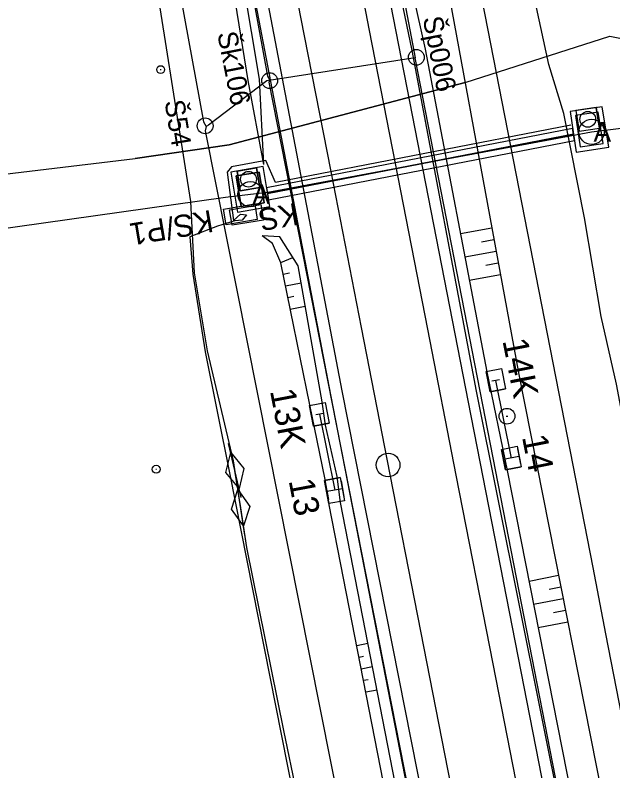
# Model space of a CAD drawing. Extents: x -545967 to -545044, y -1122650 to -1118491.
# Drawn here: x -545839.89 to -545802.07, y -1118710.23 to -1118662.41 of the extents above; entities that cross this region are included whole.
import ezdxf

# ---------------------------------------------------------------- set-up
doc = ezdxf.new("R2010")
doc.units = 0
for name, color, linetype in [('Vrstva 1', 7, 'Continuous'), ('Vrstva 1 - Koleje', 7, 'Continuous'), ('Vrstva 11 - Trakce', 7, 'Continuous'), ('Vrstva 12 - Trakce zaklady', 7, 'Continuous'), ('Vrstva 19 - Staniceni', 7, 'Continuous'), ('Vrstva 25 - silnoproud prvky', 7, 'Continuous'), ('Vrstva 26', 7, 'Continuous'), ('Vrstva 26 - silnoproud', 7, 'Continuous'), ('Vrstva 28 - zabzar', 7, 'Continuous'), ('Vrstva 31', 7, 'Continuous'), ('Vrstva 32', 7, 'Continuous'), ('Vrstva 33 - prvky sdelzar', 7, 'Continuous'), ('Vrstva 4 - Teren - stezky - prechody - plochy', 7, 'Continuous'), ('Vrstva 41', 7, 'Continuous'), ('Vrstva 42', 7, 'Continuous'), ('Vrstva 43', 7, 'Continuous'), ('Vrstva 44', 7, 'Continuous'), ('Vrstva 47', 7, 'Continuous'), ('Vrstva 48', 7, 'Continuous'), ('Vrstva 49', 7, 'Continuous'), ('Vrstva 50', 7, 'Continuous'), ('Vrstva 7 - Namezniky-vystroj', 7, 'Continuous')]:
    doc.layers.add(name, color=color, linetype=linetype)

msp = doc.modelspace()

# ---------------------------------------------------------------- linework, layer by layer
at = {"layer": 'Vrstva 1'}
for points in [[(-545825.931, -1118581.521), (-545824.016, -1118591.357), (-545817.098, -1118626.815), (-545815.58, -1118634.584), (-545810.799, -1118659.197), (-545810.531, -1118660.549), (-545805.871, -1118684.414), (-545803.343, -1118697.361)], [(-545803.343, -1118697.361), (-545802.529, -1118701.559), (-545796.372, -1118733.137), (-545788.892, -1118771.626), (-545784.123, -1118796.192), (-545777.723, -1118829.089), (-545771.163, -1118862.699), (-545764.792, -1118895.381), (-545757.603, -1118932.309), (-545753.441, -1118953.648), (-545749.904, -1118971.286), (-545746.403, -1118987.4), (-545742.64, -1119003.664), (-545739.307, -1119017.411), (-545735.997, -1119030.103), (-545730.526, -1119049.438)]]:
    msp.add_lwpolyline(points, dxfattribs=at)
at = {"layer": 'Vrstva 1 - Koleje'}
for points in [[(-545844.611, -1118524.236), (-545843.323, -1118530.854), (-545841.995, -1118537.671), (-545840.062, -1118547.589), (-545838.151, -1118557.387), (-545836.187, -1118567.479), (-545834.293, -1118577.171), (-545832.142, -1118588.194), (-545830.344, -1118597.44), (-545828.848, -1118605.077), (-545828.138, -1118608.718), (-545827.12, -1118613.935), (-545825.269, -1118623.436), (-545823.266, -1118633.717), (-545821.486, -1118642.857), (-545818.722, -1118657.024), (-545817.482, -1118663.386), (-545815.845, -1118671.798), (-545813.797, -1118682.286), (-545811.996, -1118691.52), (-545809.67, -1118703.454), (-545807.882, -1118712.632)], [(-545848.628, -1118525.023), (-545847.323, -1118531.712), (-545846.098, -1118538.003), (-545844.166, -1118547.957), (-545842.342, -1118557.292), (-545840.544, -1118566.52), (-545838.785, -1118575.544), (-545836.613, -1118586.684), (-545834.863, -1118595.653), (-545833.089, -1118604.755), (-545832.153, -1118609.557), (-545831.329, -1118613.781), (-545829.452, -1118623.418), (-545827.682, -1118632.501), (-545825.51, -1118643.639), (-545823.563, -1118653.595), (-545821.825, -1118662.539), (-545819.916, -1118672.31), (-545817.993, -1118682.172), (-545816.178, -1118691.474), (-545814.43, -1118700.429), (-545812.52, -1118710.222), (-545810.747, -1118719.317)]]:
    msp.add_lwpolyline(points, dxfattribs=at)
at = {"layer": 'Vrstva 11 - Trakce'}
for p, q in [((-545809.244, -1118685.485), (-545809.734, -1118685.582)), ((-545809.492, -1118685.534), (-545808.501, -1118690.437)), ((-545820.376, -1118687.622), (-545820.868, -1118687.715)), ((-545820.625, -1118687.669), (-545819.669, -1118692.474)), ((-545809.089, -1118690.044), (-545808.894, -1118691.025)), ((-545808.108, -1118689.849), (-545807.913, -1118690.83)), ((-545808.011, -1118690.34), (-545808.991, -1118690.534)), ((-545820.253, -1118692.075), (-545820.068, -1118693.058)), ((-545819.27, -1118691.89), (-545819.085, -1118692.873)), ((-545819.178, -1118692.382), (-545820.16, -1118692.566))]:
    msp.add_line(p, q, dxfattribs=at)
at = {"layer": 'Vrstva 12 - Trakce zaklady'}
for p, q in [((-545810.095, -1118684.967), (-545809.114, -1118684.775)), ((-545809.843, -1118686.252), (-545808.862, -1118686.06)), ((-545821.261, -1118687.11), (-545820.279, -1118686.922)), ((-545809.11, -1118689.891), (-545808.129, -1118689.697)), ((-545808.855, -1118691.18), (-545807.874, -1118690.986)), ((-545819.334, -1118691.666), (-545820.317, -1118691.85)), ((-545819.058, -1118693.137), (-545820.041, -1118693.321))]:
    msp.add_line(p, q, dxfattribs=at)
for points in [[(-545809.843, -1118686.252), (-545810.095, -1118684.967), (-545809.114, -1118684.775), (-545808.862, -1118686.06), (-545809.843, -1118686.252)], [(-545810.095, -1118684.967), (-545810.095, -1118684.967), (-545809.843, -1118686.252), (-545809.843, -1118686.252)], [(-545820.279, -1118686.922), (-545820.029, -1118688.231), (-545821.011, -1118688.419), (-545821.261, -1118687.11), (-545820.279, -1118686.922)], [(-545820.279, -1118686.922), (-545820.279, -1118686.922), (-545820.029, -1118688.231), (-545820.029, -1118688.231)], [(-545821.261, -1118687.11), (-545821.261, -1118687.11), (-545821.011, -1118688.419)], [(-545821.011, -1118688.419), (-545821.011, -1118688.419), (-545820.029, -1118688.231)], [(-545808.855, -1118691.18), (-545809.11, -1118689.891), (-545808.129, -1118689.697), (-545807.874, -1118690.986), (-545808.855, -1118691.18)], [(-545808.129, -1118689.697), (-545808.129, -1118689.697), (-545807.874, -1118690.986), (-545807.874, -1118690.986)], [(-545809.11, -1118689.891), (-545809.11, -1118689.891), (-545808.855, -1118691.18), (-545808.855, -1118691.18)], [(-545819.334, -1118691.666), (-545819.058, -1118693.137), (-545820.041, -1118693.321), (-545820.317, -1118691.85), (-545819.334, -1118691.666)], [(-545819.334, -1118691.666), (-545819.334, -1118691.666), (-545819.058, -1118693.137), (-545819.058, -1118693.137)], [(-545820.317, -1118691.85), (-545820.317, -1118691.85), (-545820.041, -1118693.321), (-545820.041, -1118693.321)]]:
    msp.add_lwpolyline(points, dxfattribs=at)
at = {"layer": 'Vrstva 19 - Staniceni'}
msp.add_circle((-545816.294, -1118690.878), 0.75, dxfattribs=at)
at = {"layer": 'Vrstva 25 - silnoproud prvky'}
for points in [[(-545826.538, -1118675.676), (-545826.706, -1118674.69), (-545824.734, -1118674.356), (-545824.566, -1118675.342), (-545826.538, -1118675.676)], [(-545826.155, -1118675.712), (-545826.323, -1118674.726), (-545824.351, -1118674.392), (-545824.183, -1118675.378), (-545826.155, -1118675.712)]]:
    msp.add_lwpolyline(points, dxfattribs=at)
at = {"layer": 'Vrstva 26'}
msp.add_lwpolyline([(-545795.14, -1118719.856), (-545797.401, -1118709.038), (-545800.896, -1118690.8), (-545801.851, -1118685.761), (-545802.818, -1118681.484), (-545803.86, -1118675.25), (-545805.172, -1118668.631), (-545806.131, -1118665.54), (-545807.231, -1118660.35), (-545808.894, -1118651.177), (-545811.62, -1118637.176), (-545812.724, -1118631.013), (-545813.605, -1118626.947), (-545815.439, -1118615.53)], dxfattribs=at)
at = {"layer": 'Vrstva 26 - silnoproud'}
for points in [[(-545795.14, -1118719.856), (-545797.401, -1118709.038), (-545800.896, -1118690.8), (-545801.851, -1118685.761), (-545802.818, -1118681.484), (-545803.86, -1118675.25), (-545805.172, -1118668.631), (-545806.131, -1118665.54), (-545807.231, -1118660.35), (-545808.894, -1118651.177), (-545811.62, -1118637.176), (-545812.724, -1118631.013), (-545813.605, -1118626.947), (-545815.439, -1118615.53)], [(-545804.723, -1118669.38), (-545823.422, -1118673.004), (-545824.024, -1118671.607), (-545826.19, -1118672.019), (-545826.479, -1118672.345), (-545826.082, -1118675.405), (-545825.636, -1118675.016), (-545825.253, -1118675.052), (-545825.524, -1118675.387), (-545825.985, -1118675.439), (-545827.078, -1118675.764), (-545828.843, -1118676.437), (-545828.656, -1118678.804), (-545827.868, -1118683.721), (-545826.321, -1118691.367), (-545821.946, -1118713.57), (-545816.92, -1118739.132), (-545813.046, -1118758.857), (-545808.289, -1118783.504), (-545803.049, -1118810.067), (-545800.897, -1118821.514), (-545796.684, -1118843.318)], [(-545804.723, -1118669.38), (-545823.422, -1118673.004)]]:
    msp.add_lwpolyline(points, dxfattribs=at)
at = {"layer": 'Vrstva 28 - zabzar'}
for p, q in [((-545825.583, -1118692.925), (-545826.385, -1118689.527)), ((-545826.55, -1118691.36), (-545826.251, -1118690.094)), ((-545826.251, -1118690.094), (-545825.418, -1118691.092)), ((-545825.418, -1118691.092), (-545825.717, -1118692.358)), ((-545825.717, -1118692.358), (-545826.55, -1118691.36)), ((-545825.351, -1118695.31), (-545825.887, -1118691.86)), ((-545826.194, -1118693.674), (-545825.797, -1118692.435)), ((-545825.797, -1118692.435), (-545825.044, -1118693.496)), ((-545825.044, -1118693.496), (-545825.441, -1118694.735)), ((-545825.441, -1118694.735), (-545826.194, -1118693.674))]:
    msp.add_line(p, q, dxfattribs=at)
for points in [[(-545825.23, -1118696.09), (-545825.619, -1118693.585), (-545825.984, -1118691.226), (-545826.08, -1118690.61), (-545827.72, -1118683.66), (-545828.55, -1118678.72), (-545828.78, -1118674.2), (-545831.46, -1118657.27), (-545836.43, -1118633.48), (-545838.77, -1118619), (-545839.17, -1118613.92), (-545839.25, -1118611.04), (-545838.43, -1118605.08), (-545838.36, -1118603.32)], [(-545759.72, -1119031.91), (-545759.89, -1119030.77), (-545763.23, -1119013.33), (-545766.25, -1118997.62), (-545768.86, -1118984.55), (-545771, -1118974.69), (-545771.8, -1118970.9), (-545773.86, -1118959.07), (-545776.3, -1118946.17), (-545780.31, -1118924.98), (-545785.87, -1118897.11), (-545790.99, -1118870.65), (-545796.29, -1118843.25), (-545799.19, -1118827.63), (-545805.85, -1118794.17), (-545808.2, -1118783.5), (-545812.82, -1118758.82), (-545816.62, -1118739.16), (-545820.43, -1118719.58), (-545822.89, -1118707.67), (-545825.23, -1118696.09)]]:
    msp.add_lwpolyline(points, dxfattribs=at)
at = {"layer": 'Vrstva 31'}
msp.add_lwpolyline([(-545850.96, -1118681.13), (-545850.51, -1118680.46), (-545848.78, -1118676.81), (-545847.44, -1118674.83), (-545847.15, -1118673.7), (-545846.77, -1118673.1), (-545844.1, -1118672.89), (-545832.3, -1118671.48), (-545826.35, -1118670.63), (-545811.42, -1118666.68), (-545802.26, -1118663.75), (-545801.2, -1118663.96), (-545800.56, -1118664.54), (-545799.84, -1118666.21), (-545798.21, -1118668.15), (-545796.54, -1118669.87), (-545795.09, -1118671.42), (-545794.4, -1118671.8)], dxfattribs=at)
msp.add_lwpolyline([(-545850.96, -1118681.13), (-545850.51, -1118680.46), (-545848.78, -1118676.81), (-545847.44, -1118674.83), (-545847.15, -1118673.7), (-545846.77, -1118673.1), (-545844.1, -1118672.89), (-545832.3, -1118671.48), (-545826.35, -1118670.63), (-545811.42, -1118666.68), (-545802.26, -1118663.75), (-545801.2, -1118663.96), (-545800.56, -1118664.54), (-545799.84, -1118666.21), (-545798.21, -1118668.15), (-545796.54, -1118669.87), (-545795.09, -1118671.42), (-545794.4, -1118671.8)], dxfattribs=at)
at = {"layer": 'Vrstva 32'}
msp.add_lwpolyline([(-545820.43, -1118719.58), (-545822.89, -1118707.67), (-545825.23, -1118696.09), (-545826.08, -1118690.61), (-545827.72, -1118683.66), (-545828.55, -1118678.72), (-545828.78, -1118674.2), (-545831.46, -1118657.27), (-545836.43, -1118633.48), (-545838.77, -1118619)], dxfattribs=at)
at = {"layer": 'Vrstva 33 - prvky sdelzar'}
msp.add_lwpolyline([(-545811.42, -1118666.68), (-545826.35, -1118670.63), (-545832.3, -1118671.48)], dxfattribs=at)
at = {"layer": 'Vrstva 4 - Teren - stezky - prechody - plochy'}
for points in [[(-545842.057, -1118523.737), (-545841.08, -1118528.803), (-545840.285, -1118532.869), (-545839.902, -1118534.493), (-545835.95, -1118554.692), (-545830.173, -1118584.852), (-545827.402, -1118599.381), (-545819.669, -1118640.626), (-545818.68, -1118644.829), (-545817.556, -1118652.409), (-545817.153, -1118653.253), (-545814.795, -1118664.646), (-545810.716, -1118686.202), (-545798.466, -1118747.292), (-545787.709, -1118802.92), (-545777.141, -1118857.583)], [(-545842.991, -1118523.919), (-545841.705, -1118530.396), (-545836.849, -1118554.447), (-545831.054, -1118584.604), (-545819.351, -1118645.264), (-545811.232, -1118686.911), (-545799.532, -1118746.647), (-545788.535, -1118802.768), (-545777.847, -1118857.696), (-545765.826, -1118919.341), (-545755.98, -1118970.183), (-545745.509, -1119023.121), (-545734.813, -1119078.883), (-545723.148, -1119138.675), (-545711.327, -1119199.256), (-545707.51, -1119218.932), (-545706.355, -1119218.803)], [(-545711.324, -1119247.435), (-545711.901, -1119243.963), (-545720.224, -1119201.665), (-545721.285, -1119195.757), (-545731.546, -1119141.712), (-545737.081, -1119112.42), (-545743.441, -1119079.103), (-545754.278, -1119022.005), (-545764.127, -1118971.243), (-545774.702, -1118917.119), (-545786.098, -1118858.181), (-545797.005, -1118803.413), (-545807.661, -1118749.422), (-545819.911, -1118686.431), (-545828.531, -1118641.36), (-545850.15, -1118530.525), (-545851.156, -1118525.517)], [(-545710.225, -1119247.22), (-545719.004, -1119201.386), (-545730.622, -1119141.385), (-545736.208, -1119112.206), (-545742.564, -1119078.927), (-545753.414, -1119021.814), (-545763.359, -1118970.942), (-545773.922, -1118916.709), (-545785.328, -1118858.188), (-545796.206, -1118802.914), (-545806.845, -1118748.63), (-545819.206, -1118686.191), (-545827.818, -1118641.013), (-545849.345, -1118530.249), (-545850.409, -1118525.371)]]:
    msp.add_lwpolyline(points, dxfattribs=at)
at = {"layer": 'Vrstva 41'}
for centre, radius in [((-545803.659, -1118669.008), 0.5), ((-545803.414, -1118669.801), 0.8), ((-545825.129, -1118672.799), 0.5), ((-545824.998, -1118673.746), 0.8)]:
    msp.add_circle(centre, radius, dxfattribs=at)
at = {"layer": 'Vrstva 42'}
msp.add_lwpolyline([(-545847.978, -1118676.939), (-545826.574, -1118673.927), (-545824.998, -1118673.746), (-545823.896, -1118673.62), (-545803.414, -1118669.801), (-545799.147, -1118669.27), (-545796.625, -1118671.347), (-545795.259, -1118671.153)], dxfattribs=at)
at = {"layer": 'Vrstva 43'}
for centre in [(-545814.504, -1118665.085), (-545823.786, -1118666.557), (-545827.871, -1118669.417)]:
    msp.add_circle(centre, 0.5, dxfattribs=at)
at = {"layer": 'Vrstva 44'}
for points in [[(-545846.223, -1118571.979), (-545846.221, -1118572.119), (-545836.892, -1118620.467), (-545827.979, -1118669.157), (-545827.809, -1118669.462), (-545827.871, -1118669.728), (-545818.616, -1118716.33), (-545818.55, -1118716.796), (-545818.473, -1118717.196), (-545808.913, -1118765.432), (-545808.826, -1118765.882), (-545808.745, -1118766.383), (-545799.375, -1118814.752), (-545799.301, -1118815.001), (-545799.29, -1118815.321), (-545789.933, -1118863.748)], [(-545823.989, -1118615.966), (-545823.909, -1118616.115), (-545814.588, -1118665.112), (-545823.538, -1118666.512), (-545823.785, -1118666.525)], [(-545833.154, -1118618.242), (-545828.365, -1118642.955), (-545827.522, -1118644.179), (-545826.938, -1118646.983), (-545827.134, -1118648.756), (-545823.92, -1118666.279), (-545823.785, -1118666.525)], [(-545805.038, -1118714.002), (-545814.588, -1118665.112)], [(-545823.785, -1118666.525), (-545823.975, -1118666.575), (-545827.65, -1118669.368), (-545827.809, -1118669.462)], [(-545814.194, -1118715.513), (-545823.815, -1118666.664), (-545823.785, -1118666.525)]]:
    msp.add_lwpolyline(points, dxfattribs=at)
at = {"layer": 'Vrstva 47'}
for p, q in [((-545803.116, -1118668.267), (-545803.117, -1118668.267)), ((-545804.406, -1118668.45), (-545804.406, -1118668.45)), ((-545802.992, -1118668.551), (-545802.992, -1118668.551)), ((-545804.439, -1118668.766), (-545804.439, -1118668.766)), ((-545823.983, -1118673.314), (-545804.623, -1118669.556)), ((-545804.505, -1118670.349), (-545804.623, -1118669.557)), ((-545802.924, -1118669.557), (-545802.924, -1118669.557)), ((-545823.918, -1118673.709), (-545804.564, -1118669.953)), ((-545804.564, -1118669.953), (-545823.918, -1118673.709)), ((-545804.202, -1118669.749), (-545804.202, -1118669.749)), ((-545823.853, -1118674.104), (-545804.504, -1118670.349)), ((-545802.674, -1118670.527), (-545802.674, -1118670.527)), ((-545804.141, -1118670.749), (-545804.141, -1118670.748)), ((-545824.609, -1118672.067), (-545824.609, -1118672.067)), ((-545825.844, -1118672.278), (-545825.844, -1118672.278)), ((-545824.447, -1118672.344), (-545824.447, -1118672.343)), ((-545825.907, -1118672.592), (-545825.907, -1118672.592)), ((-545825.653, -1118673.537), (-545825.653, -1118673.537)), ((-545824.406, -1118673.327), (-545824.406, -1118673.327)), ((-545823.983, -1118673.314), (-545823.853, -1118674.104)), ((-545824.128, -1118674.284), (-545824.128, -1118674.284)), ((-545825.582, -1118674.531), (-545825.582, -1118674.531))]:
    msp.add_line(p, q, dxfattribs=at)
for points in [[(-545804.78, -1118668.513), (-545804.393, -1118671.09), (-545802.33, -1118670.778), (-545802.743, -1118668.211)], [(-545804.406, -1118668.45), (-545804.202, -1118669.749), (-545802.924, -1118669.557), (-545803.116, -1118668.267)], [(-545804.406, -1118668.45), (-545804.202, -1118669.749), (-545802.924, -1118669.557), (-545803.117, -1118668.267)], [(-545804.439, -1118668.766), (-545804.141, -1118670.748), (-545802.674, -1118670.527), (-545802.992, -1118668.551)], [(-545804.439, -1118668.766), (-545804.141, -1118670.749), (-545802.674, -1118670.527), (-545802.992, -1118668.551)], [(-545826.252, -1118672.347), (-545825.828, -1118674.877), (-545823.783, -1118674.53), (-545824.2, -1118671.997)], [(-545825.844, -1118672.278), (-545824.609, -1118672.067), (-545824.406, -1118673.327), (-545825.653, -1118673.537)], [(-545825.844, -1118672.278), (-545825.653, -1118673.537), (-545824.406, -1118673.327), (-545824.609, -1118672.067)], [(-545825.907, -1118672.592), (-545825.582, -1118674.531), (-545824.128, -1118674.284), (-545824.447, -1118672.343)], [(-545825.907, -1118672.592), (-545824.447, -1118672.344), (-545824.128, -1118674.284), (-545825.582, -1118674.531)]]:
    msp.add_lwpolyline(points, close=True, dxfattribs=at)
at = {"layer": 'Vrstva 48'}
for p, q in [((-545809.731, -1118675.892), (-545811.717, -1118676.258)), ((-545809.596, -1118676.63), (-545810.388, -1118676.775)), ((-545809.46, -1118677.367), (-545811.435, -1118677.731)), ((-545823.081, -1118678.074), (-545822.322, -1118677.744)), ((-545809.324, -1118678.105), (-545810.112, -1118678.25)), ((-545822.929, -1118678.808), (-545822.53, -1118678.727)), ((-545809.188, -1118678.842), (-545811.153, -1118679.204)), ((-545822.78, -1118679.543), (-545821.801, -1118679.344)), ((-545822.631, -1118680.278), (-545822.247, -1118680.2)), ((-545822.481, -1118681.013), (-545821.541, -1118680.822)), ((-545805.51, -1118697.874), (-545807.376, -1118698.243)), ((-545805.364, -1118698.61), (-545806.111, -1118698.757)), ((-545805.219, -1118699.345), (-545807.086, -1118699.715)), ((-545805.073, -1118700.081), (-545805.82, -1118700.229)), ((-545804.928, -1118700.817), (-545806.796, -1118701.186)), ((-545818.274, -1118702.295), (-545817.567, -1118702.157)), ((-545818.13, -1118703.031), (-545817.847, -1118702.976)), ((-545817.986, -1118703.767), (-545817.28, -1118703.629)), ((-545817.843, -1118704.503), (-545817.56, -1118704.448)), ((-545817.699, -1118705.239), (-545816.993, -1118705.101))]:
    msp.add_line(p, q, dxfattribs=at)
at = {"layer": 'Vrstva 49'}
for points in [[(-545839.308, -1118523.198), (-545838.102, -1118529.579), (-545837.4, -1118533.485), (-545832.706, -1118555.695), (-545825.144, -1118594.377), (-545814.251, -1118651.352), (-545808.026, -1118685.152), (-545795.162, -1118750.192), (-545783.943, -1118809.71), (-545774.848, -1118856.951), (-545763.418, -1118915.038), (-545752.928, -1118968.655), (-545741.707, -1119025.946), (-545730.219, -1119081.986), (-545719.001, -1119141.326), (-545708.857, -1119196.833), (-545704.642, -1119214.146)], [(-545841.458, -1118523.619), (-545840.502, -1118528.796), (-545840.206, -1118530.169), (-545839.525, -1118532.718), (-545839.264, -1118534.264), (-545835.124, -1118554.723), (-545829.514, -1118584.885), (-545827.92, -1118592.873), (-545827.648, -1118594.262), (-545826.635, -1118599.217), (-545819.032, -1118640.374), (-545818.68, -1118644.829), (-545817.556, -1118652.409), (-545816.515, -1118653.065), (-545813.954, -1118664.567), (-545810.048, -1118684.976), (-545808.757, -1118691.228), (-545797.462, -1118748.583), (-545796.998, -1118749.953), (-545786.899, -1118802.732), (-545785.57, -1118809.023), (-545776.461, -1118857.744)], [(-545824.16, -1118671.869), (-545825.146, -1118666.549), (-545826.649, -1118657.26), (-545827.074, -1118653.958), (-545826.404, -1118653.648), (-545826.925, -1118650.894), (-545827.565, -1118650.876), (-545829.011, -1118644.138), (-545829.338, -1118642.712), (-545833.54, -1118619.463), (-545834.169, -1118615.67), (-545835.481, -1118612.652), (-545835.879, -1118611.235), (-545835.091, -1118610.526), (-545837.513, -1118600.106), (-545839.838, -1118588.301), (-545840.199, -1118586.919), (-545843.933, -1118569.058), (-545846.959, -1118554.728), (-545851.162, -1118532.2), (-545851.499, -1118530.837), (-545852.142, -1118525.71)], [(-545824.16, -1118671.869), (-545824.439, -1118666.468), (-545825.978, -1118657.274), (-545826.459, -1118654.023), (-545826.289, -1118653.729), (-545826.831, -1118650.738), (-545827.163, -1118650.609), (-545827.191, -1118650.507), (-545828.616, -1118644.06), (-545828.847, -1118642.681), (-545833.279, -1118619.551), (-545834.053, -1118615.548), (-545834.843, -1118612.356), (-545834.941, -1118610.693), (-545837.022, -1118600.001), (-545839.397, -1118588.216), (-545839.769, -1118586.656), (-545843.346, -1118569.094), (-545846.416, -1118554.054), (-545850.693, -1118532.201), (-545850.959, -1118530.818), (-545851.735, -1118525.631)], [(-545787.565, -1118859.78), (-545796.822, -1118811.001), (-545797.303, -1118809.619), (-545797.956, -1118806.406), (-545798.235, -1118804.969), (-545808.533, -1118752.244), (-545808.823, -1118750.705), (-545820.011, -1118693.395), (-545820.267, -1118691.79), (-545820.94, -1118688.496), (-545821.249, -1118687.074), (-545823.077, -1118678.082), (-545823.606, -1118676.864), (-545824.251, -1118676.389)], [(-545786.924, -1118859.548), (-545796.323, -1118810.897), (-545796.625, -1118809.56), (-545797.25, -1118806.278), (-545797.544, -1118804.841), (-545807.893, -1118752.116), (-545808.138, -1118750.544), (-545819.301, -1118693.257), (-545819.514, -1118691.615), (-545820.246, -1118688.348), (-545820.472, -1118686.892), (-545821.991, -1118678.267), (-545823.152, -1118676.433), (-545824.251, -1118676.389)]]:
    msp.add_lwpolyline(points, dxfattribs=at)
at = {"layer": 'Vrstva 50'}
for p, q in [((-545830.706, -1118665.862), (-545830.656, -1118665.862)), ((-545830.992, -1118691.145), (-545830.942, -1118691.145))]:
    msp.add_line(p, q, dxfattribs=at)
for centre in [(-545830.681, -1118665.862), (-545830.967, -1118691.145)]:
    msp.add_circle(centre, 0.25, dxfattribs=at)
at = {"layer": 'Vrstva 7 - Namezniky-vystroj'}
msp.add_line((-545808.82, -1118687.794), (-545808.72, -1118687.794), dxfattribs=at)
msp.add_circle((-545808.77, -1118687.794), 0.5, dxfattribs=at)

# ---------------------------------------------------------------- texts
at = {"layer": 'Vrstva 11 - Trakce'}
for s, rotation, p in [('14K', 281.0954, (-545809.061, -1118683.008)), ('13K', 280.8125, (-545823.771, -1118686.183)), ('14', 281.1902, (-545807.825, -1118689.099)), ('13', 280.6267, (-545822.587, -1118691.862))]:
    msp.add_text(s, height=1.6, rotation=rotation, dxfattribs=at).set_placement(p)
at = {"layer": 'Vrstva 25 - silnoproud prvky'}
for s, p in [('KS', (-545822.114, -1118674.286)), ('KS/P1', (-545827.498, -1118674.731))]:
    msp.add_text(s, height=1.4, rotation=189.6303, dxfattribs=at).set_placement(p)
at = {"layer": 'Vrstva 41'}
for p in [(-545803.294, -1118670.426), (-545824.878, -1118674.371)]:
    msp.add_text('A', height=1.25, dxfattribs=at).set_placement(p)
at = {"layer": 'Vrstva 43'}
for s, rotation, p in [('Šp006', 280.9998, (-545814.105, -1118662.602)), ('Šk106', 280.9998, (-545827.107, -1118663.566)), ('Š54', 279.317, (-545830.443, -1118667.871))]:
    msp.add_text(s, height=1.25, rotation=rotation, dxfattribs=at).set_placement(p)

doc.saveas('drawing.dxf')
